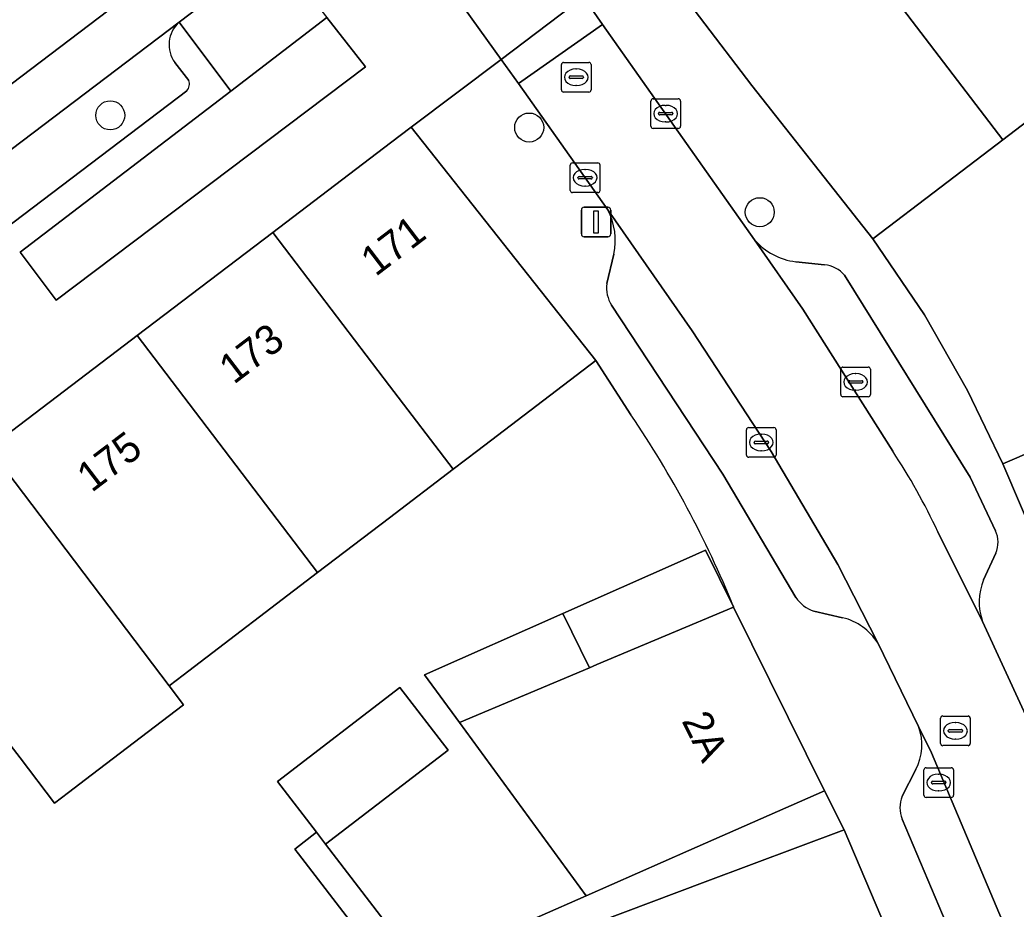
# Model space of a CAD drawing. Extents: x 159371 to 159986, y 382987 to 383597.
# Drawn here: x 159487.55 to 159521.11, y 383448.09 to 383478.07 of the extents above; entities that cross this region are included whole.
import ezdxf

# ---------------------------------------------------------------- set-up
doc = ezdxf.new("R2010")
doc.units = 0
for name, color, linetype in [('IMGEO_Boom', 7, 'Continuous'), ('IMGEO_Erf', 7, 'Continuous'), ('IMGEO_Groenvoorziening', 7, 'Continuous'), ('IMGEO_Kolk', 7, 'Continuous'), ('IMGEO_Lichtmast', 7, 'Continuous'), ('IMGEO_Muur', 7, 'Continuous'), ('IMGEO_Pand', 7, 'Continuous'), ('IMGEO_Pand_nummerreeks', 7, 'Continuous'), ('IMGEO_Parkeervlak_open', 7, 'Continuous'), ('IMGEO_Rijbaan_lokaal_gesloten', 7, 'Continuous'), ('IMGEO_Rijbaan_lokaal_open', 7, 'Continuous'), ('IMGEO_Rijbaan_regionaal_open', 7, 'Continuous'), ('IMGEO_Rioolput', 7, 'Continuous'), ('IMGEO_Voetpad_open', 7, 'Continuous')]:
    doc.layers.add(name, color=color, linetype=linetype)

msp = doc.modelspace()

# ---------------------------------------------------------------- linework, layer by layer
at = {"layer": 'IMGEO_Boom'}
for centre in [(159490.594, 383474.855), (159504.71, 383474.444), (159512.478, 383471.589)]:
    msp.add_circle(centre, 0.489, dxfattribs=at)
at = {"layer": 'IMGEO_Erf'}
for points in [[(159523.214, 383480.094), (159525.2, 383477.49), (159523.165, 383475.937), (159522.569, 383475.482), (159520.665, 383474.03), (159518.593, 383472.449), (159516.285, 383470.688), (159518.024, 383468.125), (159519.475, 383465.583), (159520.663, 383463.106), (159526.129, 383465.459), (159527.431, 383462.436), (159529.756, 383463.38), (159533.58, 383465.027), (159532.071, 383467.991), (159535.652, 383469.815), (159537.162, 383466.851), (159537.487, 383467.016), (159535.918, 383470.095), (159536.703, 383470.484), (159534.695, 383474.538), (159540.341, 383478.892)], [(159508.137, 383464.762), (159506.951, 383466.588), (159502.976, 383463.556), (159502.144, 383462.921), (159500, 383461.286), (159497.581, 383459.441), (159493.049, 383455.984), (159492.574, 383455.621), (159493.061, 383454.981), (159489.948, 383452.606), (159489.19, 383452.028), (159488.719, 383451.668), (159487.559, 383453.189), (159487.219, 383453.635)], [(159503.467, 383447.151), (159506.627, 383448.542), (159502.363, 383454.381), (159501.187, 383455.992), (159505.845, 383458.058), (159509.793, 383459.81), (159510.327, 383460.047), (159510.65, 383460.19), (159511.591, 383458.286), (159511.597, 383458.277)], [(159500.709, 383445.041), (159496.934, 383449.955), (159496.81, 383450.117), (159497.545, 383450.681), (159496.227, 383452.398), (159500.353, 383455.565), (159501.976, 383453.45), (159497.85, 383450.283), (159501.444, 383445.599)]]:
    msp.add_lwpolyline(points, dxfattribs=at)
msp.add_arc((159478.871, 383444.982), 35.324, 22.1097, 34.0537, dxfattribs=at)
at = {"layer": 'IMGEO_Groenvoorziening'}
msp.add_lwpolyline([(159494.976, 383479.535), (159494.529, 383479.229), (159492.914, 383477.993), (159494.651, 383475.67), (159497.887, 383478.152)], dxfattribs=at)
msp.add_lwpolyline([(159499.19, 383476.49), (159497.887, 383478.152), (159494.651, 383475.67), (159487.555, 383470.245), (159488.769, 383468.626)], close=True, dxfattribs=at)
at = {"layer": 'IMGEO_Kolk'}
for p, q in [((159508.807, 383474.486), (159508.807, 383475.338)), ((159508.882, 383475.412), (159509.734, 383475.412)), ((159509.295, 383475.192), (159509.32, 383475.192)), ((159509.808, 383475.338), (159509.808, 383474.486)), ((159509.066, 383474.906), (159509.066, 383474.918)), ((159509.504, 383474.869), (159509.106, 383474.869)), ((159509.109, 383474.955), (159509.507, 383474.955)), ((159509.55, 383474.918), (159509.55, 383474.906)), ((159509.318, 383474.632), (159509.293, 383474.632)), ((159509.734, 383474.412), (159508.882, 383474.412)), ((159506.094, 383472.326), (159506.094, 383473.178)), ((159506.169, 383473.252), (159507.021, 383473.252)), ((159507.095, 383473.178), (159507.095, 383472.326)), ((159506.353, 383472.746), (159506.353, 383472.758)), ((159506.396, 383472.795), (159506.794, 383472.795)), ((159506.582, 383473.032), (159506.607, 383473.032)), ((159506.837, 383472.758), (159506.837, 383472.746)), ((159506.791, 383472.709), (159506.393, 383472.709)), ((159506.605, 383472.472), (159506.58, 383472.472)), ((159507.021, 383472.252), (159506.169, 383472.252)), ((159515.207, 383465.44), (159515.207, 383466.292)), ((159515.282, 383466.366), (159516.134, 383466.366)), ((159515.695, 383466.146), (159515.72, 383466.146)), ((159516.208, 383466.292), (159516.208, 383465.44)), ((159515.466, 383465.86), (159515.466, 383465.872)), ((159515.904, 383465.823), (159515.506, 383465.823)), ((159515.509, 383465.909), (159515.907, 383465.909)), ((159515.95, 383465.872), (159515.95, 383465.86)), ((159516.134, 383465.366), (159515.282, 383465.366)), ((159515.718, 383465.586), (159515.693, 383465.586)), ((159512.03, 383463.4), (159512.03, 383464.252)), ((159512.105, 383464.326), (159512.957, 383464.326)), ((159512.518, 383464.106), (159512.543, 383464.106)), ((159513.031, 383464.252), (159513.031, 383463.4)), ((159512.289, 383463.82), (159512.289, 383463.832)), ((159512.727, 383463.783), (159512.329, 383463.783)), ((159512.332, 383463.869), (159512.73, 383463.869)), ((159512.773, 383463.832), (159512.773, 383463.82)), ((159512.541, 383463.546), (159512.516, 383463.546)), ((159512.957, 383463.326), (159512.105, 383463.326)), ((159518.006, 383451.934), (159518.006, 383452.786)), ((159518.081, 383452.86), (159518.933, 383452.86)), ((159518.494, 383452.64), (159518.519, 383452.64)), ((159519.007, 383452.786), (159519.007, 383451.934)), ((159518.265, 383452.354), (159518.265, 383452.366)), ((159518.703, 383452.317), (159518.305, 383452.317)), ((159518.308, 383452.403), (159518.706, 383452.403)), ((159518.749, 383452.366), (159518.749, 383452.354)), ((159518.517, 383452.08), (159518.492, 383452.08)), ((159518.933, 383451.86), (159518.081, 383451.86))]:
    msp.add_line(p, q, dxfattribs=at)
for points in [[(159508.807, 383474.486), (159508.807, 383475.338)], [(159508.882, 383475.412), (159509.734, 383475.412)], [(159509.808, 383475.338), (159509.808, 383474.486)], [(159509.734, 383474.412), (159508.882, 383474.412)], [(159506.094, 383472.326), (159506.094, 383473.178)], [(159506.169, 383473.252), (159507.021, 383473.252)], [(159507.095, 383473.178), (159507.095, 383472.326)], [(159507.021, 383472.252), (159506.169, 383472.252)], [(159515.207, 383465.44), (159515.207, 383466.292)], [(159515.282, 383466.366), (159516.134, 383466.366)], [(159516.208, 383466.292), (159516.208, 383465.44)], [(159516.134, 383465.366), (159515.282, 383465.366)], [(159512.03, 383463.4), (159512.03, 383464.252)], [(159512.105, 383464.326), (159512.957, 383464.326)], [(159513.031, 383464.252), (159513.031, 383463.4)], [(159512.957, 383463.326), (159512.105, 383463.326)], [(159518.006, 383451.934), (159518.006, 383452.786)], [(159518.081, 383452.86), (159518.933, 383452.86)], [(159519.007, 383452.786), (159519.007, 383451.934)], [(159518.933, 383451.86), (159518.081, 383451.86)]]:
    msp.add_lwpolyline(points, dxfattribs=at)
for centre, radius, start, end in [((159508.884, 383475.336), 0.0765, 91.552, 178.448), ((159508.884, 383475.336), 0.0765, 91.552, 178.448), ((159509.732, 383475.336), 0.0765, 1.552, 88.448), ((159509.732, 383475.336), 0.0765, 1.552, 88.448), ((159509.106, 383474.915), 0.0403, 85.8775, 175.7526), ((159509.103, 383474.905), 0.0366, 178.938, 274.7102), ((159509.507, 383474.912), 0.043, 264.8664, 352.4533), ((159509.511, 383474.917), 0.0386, 1.7309, 96.639), ((159508.884, 383474.488), 0.0765, 181.552, 268.448), ((159508.884, 383474.488), 0.0765, 181.552, 268.448), ((159509.732, 383474.488), 0.0765, 271.552, 358.448), ((159509.732, 383474.488), 0.0765, 271.552, 358.448), ((159506.171, 383473.176), 0.0765, 91.552, 178.448), ((159506.171, 383473.176), 0.0765, 91.552, 178.448), ((159507.019, 383473.176), 0.0765, 1.552, 88.448), ((159507.019, 383473.176), 0.0765, 1.552, 88.448), ((159506.393, 383472.755), 0.0403, 85.8775, 175.7526), ((159506.798, 383472.757), 0.0386, 1.7309, 96.639), ((159506.39, 383472.745), 0.0366, 178.938, 274.7102), ((159506.794, 383472.752), 0.043, 264.8664, 352.4533), ((159506.171, 383472.328), 0.0765, 181.552, 268.448), ((159506.171, 383472.328), 0.0765, 181.552, 268.448), ((159507.019, 383472.328), 0.0765, 271.552, 358.448), ((159507.019, 383472.328), 0.0765, 271.552, 358.448), ((159515.284, 383466.29), 0.0765, 91.552, 178.448), ((159515.284, 383466.29), 0.0765, 91.552, 178.448), ((159516.132, 383466.29), 0.0765, 1.552, 88.448), ((159516.132, 383466.29), 0.0765, 1.552, 88.448), ((159515.506, 383465.869), 0.0403, 85.8775, 175.7526), ((159515.503, 383465.859), 0.0366, 178.938, 274.7102), ((159515.907, 383465.866), 0.043, 264.8664, 352.4533), ((159515.911, 383465.871), 0.0386, 1.7309, 96.639), ((159515.284, 383465.442), 0.0765, 181.552, 268.448), ((159515.284, 383465.442), 0.0765, 181.552, 268.448), ((159516.132, 383465.442), 0.0765, 271.552, 358.448), ((159516.132, 383465.442), 0.0765, 271.552, 358.448), ((159512.107, 383464.25), 0.0765, 91.552, 178.448), ((159512.107, 383464.25), 0.0765, 91.552, 178.448), ((159512.955, 383464.25), 0.0765, 1.552, 88.448), ((159512.955, 383464.25), 0.0765, 1.552, 88.448), ((159512.329, 383463.829), 0.0403, 85.8775, 175.7526), ((159512.326, 383463.819), 0.0366, 178.938, 274.7102), ((159512.73, 383463.826), 0.043, 264.8664, 352.4533), ((159512.734, 383463.831), 0.0386, 1.7309, 96.639), ((159512.107, 383463.402), 0.0765, 181.552, 268.448), ((159512.107, 383463.402), 0.0765, 181.552, 268.448), ((159512.955, 383463.402), 0.0765, 271.552, 358.448), ((159512.955, 383463.402), 0.0765, 271.552, 358.448), ((159518.083, 383452.784), 0.0765, 91.552, 178.448), ((159518.083, 383452.784), 0.0765, 91.552, 178.448), ((159518.931, 383452.784), 0.0765, 1.552, 88.448), ((159518.931, 383452.784), 0.0765, 1.552, 88.448), ((159518.305, 383452.363), 0.0403, 85.8775, 175.7526), ((159518.302, 383452.353), 0.0366, 178.938, 274.7102), ((159518.706, 383452.36), 0.043, 264.8664, 352.4533), ((159518.71, 383452.365), 0.0386, 1.7309, 96.639), ((159518.083, 383451.936), 0.0765, 181.552, 268.448), ((159518.083, 383451.936), 0.0765, 181.552, 268.448), ((159518.931, 383451.936), 0.0765, 271.552, 358.448), ((159518.931, 383451.936), 0.0765, 271.552, 358.448)]:
    msp.add_arc(centre, radius, start, end, dxfattribs=at)
for centre, major_axis, ratio, start_param, end_param in [((159509.294, 383474.912), (-0.387, 0.002), 0.722429, 4.712389, 7.853982), ((159509.319, 383474.912), (-0.39, 0.002), 0.717154, 1.570796, 4.712389), ((159506.581, 383472.752), (-0.387, 0.002), 0.722429, 4.712389, 7.853982), ((159506.606, 383472.752), (-0.39, 0.002), 0.717154, 1.570796, 4.712389), ((159515.694, 383465.866), (-0.387, 0.002), 0.722429, 4.712389, 7.853982), ((159515.719, 383465.866), (-0.39, 0.002), 0.717154, 1.570796, 4.712389), ((159512.517, 383463.826), (-0.387, 0.002), 0.722429, 4.712389, 7.853982), ((159512.542, 383463.826), (-0.39, 0.002), 0.717154, 1.570796, 4.712389), ((159518.493, 383452.36), (-0.387, 0.002), 0.722429, 4.712389, 7.853982), ((159518.518, 383452.36), (-0.39, 0.002), 0.717154, 1.570796, 4.712389)]:
    msp.add_ellipse(centre, major_axis=major_axis, ratio=ratio, start_param=start_param, end_param=end_param, dxfattribs=at)
at = {"layer": 'IMGEO_Lichtmast'}
for p, q in [((159506.567, 383471.759), (159507.357, 383471.759)), ((159507.357, 383471.759), (159506.567, 383471.759)), ((159506.467, 383470.859), (159506.467, 383471.659)), ((159506.467, 383471.659), (159506.467, 383470.859)), ((159507.457, 383471.659), (159507.457, 383470.859)), ((159507.457, 383470.859), (159507.457, 383471.659)), ((159507.357, 383470.759), (159506.567, 383470.759)), ((159506.567, 383470.759), (159507.357, 383470.759))]:
    msp.add_line(p, q, dxfattribs=at)
msp.add_lwpolyline([(159506.887, 383471.634), (159507.037, 383471.634), (159507.037, 383470.884), (159506.887, 383470.884), (159506.887, 383471.634)], dxfattribs=at)
for centre, start, end in [((159506.567, 383471.659), 90, 180), ((159506.567, 383471.659), 90, 180), ((159507.357, 383471.659), 0, 90), ((159507.357, 383471.659), 360, 90), ((159506.567, 383470.859), 180, 270), ((159506.567, 383470.859), 180, 270), ((159507.357, 383470.859), 270, 0), ((159507.357, 383470.859), 270, 0)]:
    msp.add_arc(centre, 0.1, start, end, dxfattribs=at)
at = {"layer": 'IMGEO_Muur'}
for points in [[(159516.285, 383470.688), (159518.024, 383468.125), (159519.475, 383465.583), (159520.663, 383463.106)], [(159506.951, 383466.588), (159508.137, 383464.762)]]:
    msp.add_lwpolyline(points, dxfattribs=at)
msp.add_arc((159478.871, 383444.982), 35.324, 22.1097, 34.0537, dxfattribs=at)
at = {"layer": 'IMGEO_Pand'}
for points in [[(159517.687, 383487.34), (159513.142, 383483.892), (159520.665, 383474.03), (159522.569, 383475.482), (159523.165, 383475.937), (159525.2, 383477.49), (159523.214, 383480.094)], [(159513.142, 383483.892), (159508.68, 383480.507), (159512.213, 383475.86), (159516.285, 383470.688), (159518.593, 383472.449), (159520.665, 383474.03)], [(159500.731, 383474.456), (159500.039, 383473.929), (159496.066, 383470.906), (159500, 383465.737), (159502.144, 383462.921), (159502.976, 383463.556), (159506.951, 383466.588)], [(159500, 383465.737), (159496.066, 383470.906), (159491.499, 383467.432), (159497.581, 383459.441), (159500, 383461.286), (159502.144, 383462.921)], [(159491.499, 383467.432), (159491.306, 383467.285), (159486.499, 383463.639), (159492.574, 383455.621), (159493.049, 383455.984), (159497.581, 383459.441)], [(159520.663, 383463.106), (159521.965, 383460.082), (159527.431, 383462.436), (159526.129, 383465.459)], [(159486.499, 383463.639), (159481.987, 383460.213), (159487.219, 383453.635), (159487.559, 383453.189), (159488.719, 383451.668), (159489.19, 383452.028), (159489.948, 383452.606), (159493.061, 383454.981), (159492.574, 383455.621)], [(159511.597, 383458.277), (159511.591, 383458.286), (159510.65, 383460.19), (159510.327, 383460.047), (159509.793, 383459.81), (159505.845, 383458.058), (159506.74, 383456.228), (159506.991, 383456.334)], [(159505.845, 383458.058), (159501.187, 383455.992), (159502.363, 383454.381), (159506.74, 383456.228)], [(159511.597, 383458.277), (159506.991, 383456.334), (159506.74, 383456.228), (159502.363, 383454.381), (159506.627, 383448.542), (159510.087, 383450.065), (159514.663, 383452.079)], [(159501.976, 383453.45), (159500.353, 383455.565), (159496.227, 383452.398), (159497.545, 383450.681), (159497.85, 383450.283)], [(159517.64, 383445.309), (159515.325, 383450.76), (159510.643, 383449.007), (159507.002, 383447.644), (159508.102, 383444.708), (159505.966, 383443.908), (159507.119, 383440.828)]]:
    msp.add_lwpolyline(points, close=True, dxfattribs=at)
at = {"layer": 'IMGEO_Parkeervlak_open'}
for points in [[(159492.914, 383477.993), (159477.407, 383466.243)], [(159493.24, 383476.031), (159492.772, 383476.635)], [(159479.198, 383465.082), (159493.171, 383475.68)], [(159516.451, 383457.066), (159515.11, 383459.706), (159512.865, 383463.523), (159510.201, 383467.59), (159507.358, 383471.672)], [(159512.306, 383470.663), (159513.931, 383468.315), (159516.957, 383463.53)], [(159507.562, 383470.179), (159507.328, 383469.184)], [(159514.662, 383469.819), (159513.69, 383469.92)], [(159520.424, 383460.847), (159519.564, 383462.655), (159515.339, 383469.467)], [(159507.483, 383468.454), (159511.23, 383462.753), (159513.691, 383458.604)], [(159518.479, 383460.814), (159519.986, 383457.784)], [(159520.016, 383459.193), (159520.431, 383460.094)], [(159514.301, 383458.134), (159515.271, 383457.918)], [(159532.286, 383418.286), (159522.834, 383442.514), (159518.267, 383453.359), (159517.828, 383454.245)], [(159517.738, 383452.803), (159517.275, 383451.896)], [(159517.271, 383451.128), (159521.357, 383441.485), (159529.485, 383420.516)]]:
    msp.add_lwpolyline(points, dxfattribs=at)
for centre, radius, start, end in [((159493.594, 383477.235), 1.018, 131.9285, 216.1326), ((159492.923, 383475.911), 0.339, 316.9906, 20.7665), ((159505.381, 383470.641), 2.229, 348.0283, 27.5329), ((159513.924, 383472.016), 2.109, 219.9103, 263.6315), ((159514.527, 383468.733), 1.094, 42.1264, 82.9301), ((159508.424, 383469.035), 1.106, 172.2791, 211.6959), ((159499.298, 383451.85), 21.172, 25.049, 33.4821), ((159519.599, 383460.463), 0.91, 336.1049, 24.9604), ((159521.845, 383458.449), 1.974, 157.871, 199.6895), ((159514.681, 383459.258), 1.187, 213.4526, 251.3195), ((159514.821, 383456.051), 1.92, 31.9017, 76.4372), ((159516.195, 383453.623), 1.747, 332.0088, 20.8485), ((159518.261, 383451.507), 1.06, 158.4628, 200.9404)]:
    msp.add_arc(centre, radius, start, end, dxfattribs=at)
at = {"layer": 'IMGEO_Rijbaan_lokaal_gesloten'}
msp.add_lwpolyline([(159427.129, 383428.173), (159427.859, 383428.709), (159429.817, 383430.216), (159435.428, 383434.471), (159435.864, 383434.831), (159435.968, 383434.909), (159451.798, 383446.86), (159453.424, 383448.091), (159457.863, 383451.442), (159460.832, 383453.708), (159476.264, 383465.375), (159476.315, 383465.414), (159477.407, 383466.243), (159492.914, 383477.993), (159494.529, 383479.229), (159494.976, 383479.535), (159493.954, 383480.98), (159492.14, 383479.622), (159434.929, 383436.186), (159424.779, 383428.544)], dxfattribs=at)
at = {"layer": 'IMGEO_Rijbaan_lokaal_open'}
for points in [[(159502.534, 383478.452), (159503.767, 383476.741), (159506.539, 383478.849), (159505.484, 383480.364)], [(159516.957, 383463.53), (159513.931, 383468.315), (159512.306, 383470.663), (159507.184, 383477.923), (159504.352, 383475.93), (159507.358, 383471.672), (159510.201, 383467.59), (159512.865, 383463.523), (159515.11, 383459.706), (159516.451, 383457.066), (159517.828, 383454.245), (159518.267, 383453.359), (159522.834, 383442.514), (159532.286, 383418.286), (159532.614, 383417.448), (159539.935, 383420.241), (159537.852, 383425.657)], [(159522.767, 383451.739), (159519.986, 383457.784), (159518.479, 383460.814)]]:
    msp.add_lwpolyline(points, dxfattribs=at)
msp.add_lwpolyline([(159507.184, 383477.923), (159506.539, 383478.849), (159503.767, 383476.741), (159504.352, 383475.93)], close=True, dxfattribs=at)
msp.add_arc((159499.298, 383451.85), 21.172, 25.049, 33.4821, dxfattribs=at)
at = {"layer": 'IMGEO_Rijbaan_regionaal_open'}
msp.add_lwpolyline([(159424.779, 383428.544), (159434.929, 383436.186), (159492.14, 383479.622), (159490.734, 383481.412), (159453.87, 383453.311), (159440.381, 383444.531), (159430.515, 383438.11), (159401.313, 383419.104)], dxfattribs=at)
at = {"layer": 'IMGEO_Rioolput'}
for p, q in [((159505.794, 383475.713), (159505.794, 383476.565)), ((159505.869, 383476.639), (159506.721, 383476.639)), ((159506.795, 383476.565), (159506.795, 383475.713)), ((159506.053, 383476.133), (159506.053, 383476.145)), ((159506.096, 383476.182), (159506.494, 383476.182)), ((159506.282, 383476.419), (159506.307, 383476.419)), ((159506.537, 383476.145), (159506.537, 383476.133)), ((159506.491, 383476.096), (159506.093, 383476.096)), ((159506.305, 383475.859), (159506.28, 383475.859)), ((159506.721, 383475.639), (159505.869, 383475.639)), ((159518.571, 383453.677), (159518.571, 383454.529)), ((159518.646, 383454.603), (159519.498, 383454.603)), ((159519.059, 383454.383), (159519.084, 383454.383)), ((159519.572, 383454.529), (159519.572, 383453.677)), ((159518.83, 383454.097), (159518.83, 383454.109)), ((159519.268, 383454.06), (159518.87, 383454.06)), ((159518.873, 383454.146), (159519.271, 383454.146)), ((159519.314, 383454.109), (159519.314, 383454.097)), ((159519.082, 383453.823), (159519.057, 383453.823)), ((159519.498, 383453.603), (159518.646, 383453.603))]:
    msp.add_line(p, q, dxfattribs=at)
for points in [[(159505.794, 383475.713), (159505.794, 383476.565)], [(159505.869, 383476.639), (159506.721, 383476.639)], [(159506.795, 383476.565), (159506.795, 383475.713)], [(159506.721, 383475.639), (159505.869, 383475.639)], [(159518.571, 383453.677), (159518.571, 383454.529)], [(159518.646, 383454.603), (159519.498, 383454.603)], [(159519.572, 383454.529), (159519.572, 383453.677)], [(159519.498, 383453.603), (159518.646, 383453.603)]]:
    msp.add_lwpolyline(points, dxfattribs=at)
for centre, radius, start, end in [((159505.871, 383476.563), 0.0765, 91.552, 178.448), ((159505.871, 383476.563), 0.0765, 91.552, 178.448), ((159506.719, 383476.563), 0.0765, 1.552, 88.448), ((159506.719, 383476.563), 0.0765, 1.552, 88.448), ((159506.093, 383476.142), 0.0403, 85.8775, 175.7526), ((159506.09, 383476.132), 0.0366, 178.938, 274.7102), ((159506.494, 383476.139), 0.043, 264.8664, 352.4533), ((159506.498, 383476.144), 0.0386, 1.7309, 96.639), ((159505.871, 383475.715), 0.0765, 181.552, 268.448), ((159505.871, 383475.715), 0.0765, 181.552, 268.448), ((159506.719, 383475.715), 0.0765, 271.552, 358.448), ((159506.719, 383475.715), 0.0765, 271.552, 358.448), ((159518.648, 383454.527), 0.0765, 91.552, 178.448), ((159518.648, 383454.527), 0.0765, 91.552, 178.448), ((159519.496, 383454.527), 0.0765, 1.552, 88.448), ((159519.496, 383454.527), 0.0765, 1.552, 88.448), ((159518.87, 383454.106), 0.0403, 85.8775, 175.7526), ((159518.867, 383454.096), 0.0366, 178.938, 274.7102), ((159519.271, 383454.103), 0.043, 264.8664, 352.4533), ((159519.275, 383454.108), 0.0386, 1.7309, 96.639), ((159518.648, 383453.679), 0.0765, 181.552, 268.448), ((159518.648, 383453.679), 0.0765, 181.552, 268.448), ((159519.496, 383453.679), 0.0765, 271.552, 358.448), ((159519.496, 383453.679), 0.0765, 271.552, 358.448)]:
    msp.add_arc(centre, radius, start, end, dxfattribs=at)
for centre, major_axis, ratio, start_param, end_param in [((159506.281, 383476.139), (-0.387, 0.002), 0.722429, 4.712389, 7.853982), ((159506.306, 383476.139), (-0.39, 0.002), 0.717154, 1.570796, 4.712389), ((159519.058, 383454.103), (-0.387, 0.002), 0.722429, 4.712389, 7.853982), ((159519.083, 383454.103), (-0.39, 0.002), 0.717154, 1.570796, 4.712389)]:
    msp.add_ellipse(centre, major_axis=major_axis, ratio=ratio, start_param=start_param, end_param=end_param, dxfattribs=at)
at = {"layer": 'IMGEO_Voetpad_open'}
for points in [[(159524.622, 383454.046), (159522.471, 383458.851), (159521.965, 383460.082), (159520.663, 383463.106), (159519.475, 383465.583), (159518.024, 383468.125), (159516.285, 383470.688), (159512.213, 383475.86), (159508.68, 383480.507), (159506.539, 383478.849), (159507.184, 383477.923), (159512.306, 383470.663)], [(159496.321, 383480.15), (159497.887, 383478.152), (159499.19, 383476.49), (159488.769, 383468.626), (159487.555, 383470.245), (159494.651, 383475.67), (159492.914, 383477.993)], [(159452.734, 383439.412), (159453.314, 383438.652), (159459.401, 383443.31), (159459.554, 383443.427), (159459.676, 383443.267), (159461.209, 383444.451), (159461.945, 383445.02), (159467.302, 383449.158), (159468.26, 383449.798), (159471.132, 383451.972), (159474.69, 383454.671), (159477.515, 383456.814), (159481.199, 383459.608), (159481.987, 383460.213), (159486.499, 383463.639), (159491.306, 383467.285), (159491.499, 383467.432), (159496.066, 383470.906), (159500.039, 383473.929), (159500.731, 383474.456), (159503.767, 383476.741), (159502.534, 383478.452)], [(159492.772, 383476.635), (159493.24, 383476.031)], [(159507.358, 383471.672), (159504.352, 383475.93), (159503.767, 383476.741), (159500.731, 383474.456), (159506.951, 383466.588), (159508.137, 383464.762)], [(159493.171, 383475.68), (159479.198, 383465.082)], [(159507.328, 383469.184), (159507.562, 383470.179)], [(159513.69, 383469.92), (159514.662, 383469.819)], [(159515.339, 383469.467), (159519.564, 383462.655), (159520.424, 383460.847)], [(159513.691, 383458.604), (159511.23, 383462.753), (159507.483, 383468.454)], [(159520.431, 383460.094), (159520.016, 383459.193)], [(159511.597, 383458.277), (159514.663, 383452.079), (159515.325, 383450.76), (159517.64, 383445.309), (159519.89, 383440.01), (159520.124, 383439.458), (159521.93, 383434.635), (159523.946, 383429.25), (159526.015, 383423.724), (159528.9, 383416.051), (159532.614, 383417.448), (159532.286, 383418.286)], [(159515.271, 383457.918), (159514.301, 383458.134)], [(159519.986, 383457.784), (159522.767, 383451.739), (159524.331, 383448.016), (159525.442, 383448.447), (159527.568, 383443.436), (159526.421, 383443.01), (159526.492, 383442.856)], [(159517.828, 383454.245), (159516.451, 383457.066)], [(159517.275, 383451.896), (159517.738, 383452.803)], [(159507.002, 383447.644), (159510.643, 383449.007), (159515.325, 383450.76), (159514.663, 383452.079), (159510.087, 383450.065), (159506.627, 383448.542), (159503.467, 383447.151)], [(159529.485, 383420.516), (159521.357, 383441.485), (159517.271, 383451.128)], [(159501.444, 383445.599), (159497.85, 383450.283), (159497.545, 383450.681), (159496.81, 383450.117), (159496.934, 383449.955), (159500.709, 383445.041)]]:
    msp.add_lwpolyline(points, dxfattribs=at)
for centre, radius, start, end in [((159493.594, 383477.235), 1.018, 131.9285, 216.1326), ((159492.923, 383475.911), 0.339, 316.9906, 20.7665), ((159505.381, 383470.641), 2.229, 348.0283, 27.5329), ((159513.924, 383472.016), 2.109, 219.9103, 263.6315), ((159514.527, 383468.733), 1.094, 42.1264, 82.9301), ((159508.424, 383469.035), 1.106, 172.2791, 211.6959), ((159478.871, 383444.982), 35.324, 22.1097, 34.0537), ((159519.599, 383460.463), 0.91, 336.1049, 24.9604), ((159521.845, 383458.449), 1.974, 157.871, 199.6895), ((159514.681, 383459.258), 1.187, 213.4526, 251.3195), ((159514.821, 383456.051), 1.92, 31.9017, 76.4372), ((159516.195, 383453.623), 1.747, 332.0088, 20.8485), ((159518.261, 383451.507), 1.06, 158.4628, 200.9404)]:
    msp.add_arc(centre, radius, start, end, dxfattribs=at)

# ---------------------------------------------------------------- texts
at = {"layer": 'IMGEO_Pand_nummerreeks'}
for s, rotation, p in [('171', 37.2881, (159499.533, 383469.398)), ('173', 37.2709, (159494.757, 383465.763)), ('175', 37.2594, (159489.968, 383462.118)), ('2A', 296.3215, (159509.834, 383454.444))]:
    msp.add_text(s, height=1, rotation=rotation, dxfattribs=at).set_placement(p)

doc.saveas('drawing.dxf')
